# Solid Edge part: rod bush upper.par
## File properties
Author: Robert a Rhodes jr
Template: Normal.par
Last saved by: Cadcim
Revision: 5
Application: Solid Edge
Accuracy: 0.99
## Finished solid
Body 1: solid body, 4 faces, 4 edges, 0 vertices.
  Faces by surface: cylinder 2, plane 2
  Edges by curve: circle 4
Bounding box of the edges (mm): 24.000 x 24.000 x 42.000, from (-12, -12, -42) to (12, 12, 0).
Cylindrical faces by radius (mm): R11 x1, R12 x1
Planar faces by outward normal: +z 1, -z 1
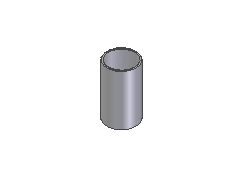
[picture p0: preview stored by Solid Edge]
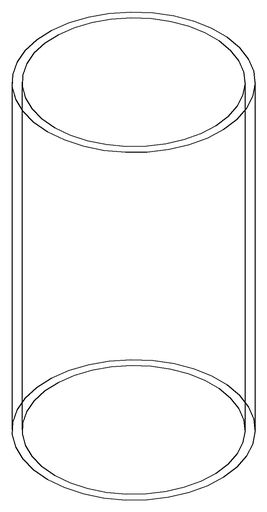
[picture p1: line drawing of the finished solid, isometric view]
